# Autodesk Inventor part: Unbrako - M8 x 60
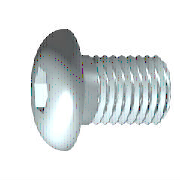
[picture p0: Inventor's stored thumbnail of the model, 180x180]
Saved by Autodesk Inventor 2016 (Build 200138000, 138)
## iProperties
IsCustomPart: 0
Created: 2015-02
Part Number: Unbrako - M8 x 60
Material: Steel, Mild
Description: Hexagon Socket Button Head Cap Screw
Document SubType Name: Modeling
Standard: Unbrako
Designer: stank
Standards Organization: AS
Language: en-US
Size Designation: M8 x 60
Categories: <MemberInstance><Categories><Category DisplayName="Fasteners" InternalName="e4da775c-781d-43d5-af7c-5136215cf5a6" Mnemonic="FSTN"><Category DisplayName="Bolts"
Density: 7.85 g/cm^3
Appearance: Semi-Polished
Author: stank
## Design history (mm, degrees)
sketch "Sketch1"
  geometry: L1 (-0.133, 0)-(60, 0); L2 (60, 0)-(60, 4); L3 (60, 4)-(3.125, 4); L4 (3.125, 4)-(2.358, 4); L5 (2.358, 4)-(0, 4); L6 (0, 4)-(0, 7); L7 (0, 7)-(-4.4, 7); L8 (-4.4, 7)-(-4.4, 2.887); L9 (-4.4, 2.887)-(-1.8, 2.887); L10 (-1.8, 2.887)-(-0.133, 0); L11 (-21, 0)-(56, 0) reference; L12 (0, -1.6)-(0, 9.6) reference; L13 (3.125, 4)-(0, 4)
  constraints: 22 end point, 6 parallel, 2 collinear, 2 perpendicular, 1 horizontal, 1 midpoint
  dimensions: "d1" = 56.875 distance from line of L3.end L2 (= GEL); "d2" = 0.76691 distance of L4.end L3.end (computed from GAL); "d3" = 4.4 distance between parallel lines of L8 L6 (= KOH); "d4" = 2.6 distance of L8.end L9.end (= INTI); "d5" = 60 deg angle of L10 L1; "d6" = 8 diameter of L3 L1 (= GD); "d7" = 8 diameter of L5 L1 (= BDM); "d8" = 5.7735 diameter of L9 L1 (= 1.1547 x SW); "d9" = 14 diameter of L7 L1 (= KOD); "d26" = 60 distance between parallel lines of L12 L2 (= NLG)
revolve "Body" sketch "Sketch1" stored, may be unused: angle "d10" = 90 deg
sketch "Sketch2"
  geometry: L1 (0, -9.8)-(0, 9.8) reference; L2 (-9.8, 0)-(9.8, 0) reference; L3 (2.887, 0)-(1.443, -2.5); L4 (1.443, -2.5)-(-1.443, -2.5); L5 (-1.443, -2.5)-(-2.887, 0); L6 (-2.887, 0)-(-1.443, 2.5); L7 (-1.443, 2.5)-(1.443, 2.5); L8 (1.443, 2.5)-(2.887, 0); 2 further points
  constraints: 12 end point, 1 coincident, 1 horizontal alignment, 1 point on line, 12 other
extrude "Slot" join sketch "Sketch2" stored distance "d11" = 10; taper "d12" = 0 deg
workplane "Work Plane1"
fillet "Fillet2" dims "d30" = 0.1 (= R)
body "Solid1"
fillet "Fillet1" dims "d17" = 2.6 (= RR)
feature "Thread" dims "d13" = 56.875 (= GEL), "d14" = 0
chamfer "Chamfer1" distance "d15" = 0.76681 (= -0.5 x SPD + 0.5 x GD); stored, may be unused: second distance "d16" = 0.76681 (= GUL), angle "d27" = 45 deg
other parameters: "GD" = 8 (= NND) [user parameter; used in 2 equation terms], "NLG" = 60 [user parameter; used in 1 equation term], "GEL" = 56.875 [user parameter; used in 2 equation terms], "KOD" = 14 [user parameter; used in 1 equation term], "KOH" = 4.4 [user parameter; used in 1 equation term], "INTI" = 2.6 [user parameter; used in 2 equation terms], "GAL" = 0.76681 (= 0.61345 x PTC) [user parameter; used in 1 equation term], "GUL" = 0.76681 (= 0.61345 x PTC) [user parameter; used in 1 equation term], "BDM" = 8 (= NND) [user parameter; used in 1 equation term], "SW" = 5 [user parameter; used in 2 equation terms], "RR" = 2.6 (= INTI) [user parameter; used in 1 equation term], "SPD" = 6.46637 (= NND - 1.2269 x PTC) [user parameter; used in 1 equation term], "d19" = 0, "d28" = 0, "d29" = 0, "R" = 0.1 [user parameter; used in 1 equation term], "KR" = 7.5 [user parameter], "GD1" = 6.46637 (= THREADDIA - 1.2269 x PTC) [user parameter], "THREADDIA" = 8 [user parameter; used in 1 equation term], "FAWI" = 45 deg [user parameter], "TPU" = 8 (computed from PTC) [user parameter], "PTC" = 1.25 [user parameter; used in 5 equation terms], "KOH1" = 2.6 [user parameter], "NND" = 8 [user parameter; used in 3 equation terms], "TOA" = 30 deg [user parameter], "E0" = 5.775 (= 1.155 x SW) [user parameter]
